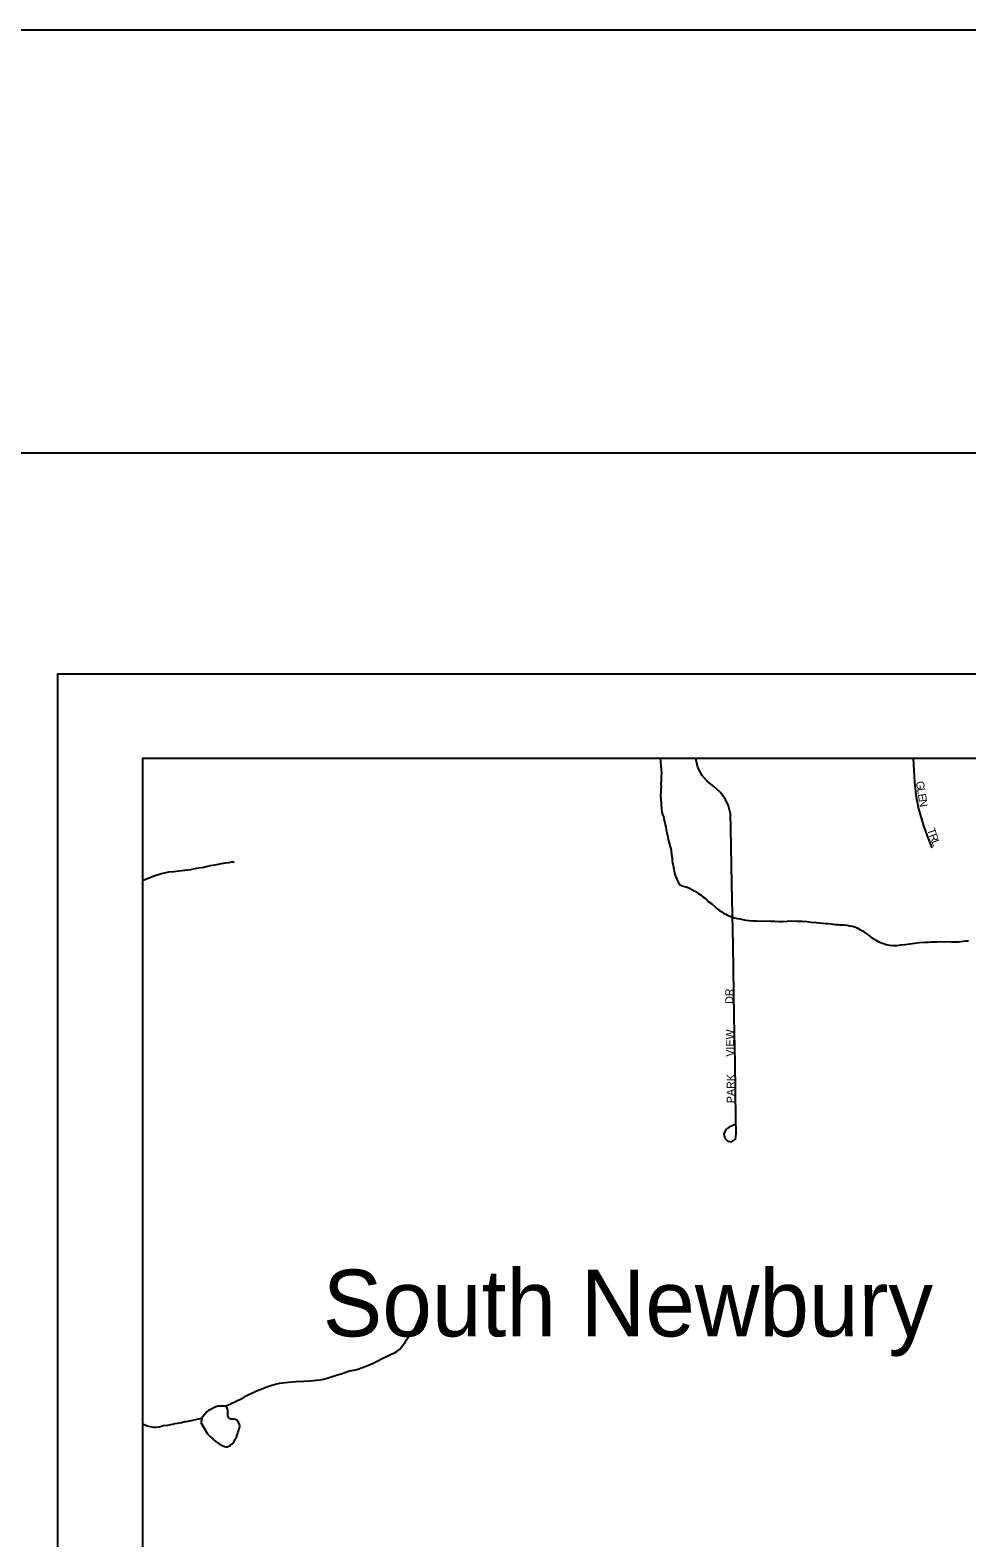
# Model space of a CAD drawing. Extents: x 0 to 34, y 0 to 22.
# Drawn here: x 2.229 to 3.337, y 20.216 to 22 of the extents above; entities that cross this region are included whole.
import ezdxf

# ---------------------------------------------------------------- set-up
doc = ezdxf.new("R2010")
doc.units = 0
for name, color, linetype in [('GM_X_County', 7, 'Continuous'), ('GM_X_Minor_Lake', 7, 'Continuous'), ('GM_X_Minor_River', 7, 'Continuous'), ('GM_X_Township', 7, 'Continuous'), ('GM_X_Township_Subdivision', 7, 'Continuous'), ('GM_X_Township_Subdivision_Text', 7, 'Continuous'), ('GM_X_Unincorporated_Text', 7, 'Continuous'), ('SH_Border', 7, 'Continuous'), ('SH_Cut_Line', 7, 'Continuous'), ('SH_Data', 7, 'Continuous')]:
    doc.layers.add(name, color=color, linetype=linetype)

msp = doc.modelspace()

# ---------------------------------------------------------------- linework, layer by layer
at = {"layer": 'GM_X_County'}
msp.add_lwpolyline([(9.1622, 14.342), (9.1622, 21.1385), (2.3622, 21.1385), (2.3622, 14.3385), (9.0003, 14.3385)], dxfattribs=at)
at = {"layer": 'GM_X_Minor_Lake'}
for points in [[(2.4565, 20.3721), (2.4538, 20.3722), (2.4515, 20.3721), (2.4489, 20.3713), (2.4455, 20.3697), (2.4428, 20.3681), (2.4406, 20.3673), (2.438, 20.3654), (2.4357, 20.3627), (2.4342, 20.3607), (2.4324, 20.358), (2.4317, 20.355), (2.431, 20.3527)], [(2.431, 20.3527), (2.4389, 20.3392), (2.4408, 20.3373), (2.4428, 20.3355), (2.4455, 20.3332), (2.4474, 20.3314), (2.4494, 20.3299), (2.4517, 20.3284), (2.4544, 20.3266), (2.4571, 20.3251), (2.4605, 20.3241), (2.4624, 20.3241), (2.4658, 20.3257), (2.4681, 20.3277), (2.4707, 20.3304), (2.4717, 20.3331), (2.4732, 20.3354), (2.4743, 20.3388), (2.475, 20.3407), (2.4761, 20.3442), (2.4768, 20.3465), (2.4771, 20.3484), (2.4767, 20.3503), (2.4759, 20.3525), (2.4743, 20.3552), (2.472, 20.3562), (2.4701, 20.3566), (2.4667, 20.3565), (2.4644, 20.3584), (2.4632, 20.3606), (2.4631, 20.3629), (2.4631, 20.3652), (2.463, 20.3674), (2.4622, 20.3697), (2.4603, 20.3719), (2.4565, 20.3721)]]:
    msp.add_lwpolyline(points, dxfattribs=at)
at = {"layer": 'GM_X_Minor_River'}
for points in [[(2.9745, 21.1385), (2.9745, 21.1381), (2.975, 21.1355), (2.975, 21.1332), (2.9755, 21.1302), (2.9759, 21.1256), (2.976, 21.1211), (2.9757, 21.1165), (2.9758, 21.1123), (2.9755, 21.1081), (2.9756, 21.1051), (2.9753, 21.1028), (2.9753, 21.1005), (2.9754, 21.0986), (2.9751, 21.0956), (2.9751, 21.0933), (2.9752, 21.0906), (2.9752, 21.0887), (2.9756, 21.0857), (2.9757, 21.0838), (2.9762, 21.0789), (2.9766, 21.0747), (2.9775, 21.0721), (2.9783, 21.0698), (2.9787, 21.0672), (2.9791, 21.0653), (2.9799, 21.0626), (2.9804, 21.06), (2.9812, 21.0573), (2.9816, 21.0539), (2.9825, 21.0509), (2.9833, 21.0471), (2.9842, 21.0426), (2.9854, 21.0369), (2.9867, 21.0328), (2.9875, 21.0297), (2.9875, 21.0278), (2.988, 21.0252), (2.9889, 21.0195), (2.9889, 21.0176), (2.9893, 21.0146), (2.9898, 21.0119), (2.9906, 21.0074), (2.9915, 21.0028), (2.9927, 20.9991), (2.9943, 20.9957), (2.9951, 20.9934), (2.9963, 20.9912), (2.9975, 20.9893), (3.0006, 20.9878), (3.0032, 20.9868), (3.0063, 20.9861)], [(2.3622, 20.9939), (2.3768, 20.9997), (2.3806, 21.001), (2.3844, 21.0022), (2.3885, 21.003), (2.3934, 21.0043), (2.3991, 21.0048), (2.4052, 21.0053), (2.412, 21.0062), (2.4193, 21.0071), (2.4261, 21.0084), (2.4348, 21.0097), (2.4424, 21.0118), (2.4499, 21.0131), (2.4556, 21.014), (2.4602, 21.0148), (2.4643, 21.0153), (2.4678, 21.0162), (2.4693, 21.0162), (2.4704, 21.0162)], [(3.0063, 20.9861), (3.0094, 20.985), (3.0121, 20.9835), (3.0155, 20.9813), (3.019, 20.9791), (3.0221, 20.9769), (3.0252, 20.9747), (3.0283, 20.9725), (3.0314, 20.9691), (3.0356, 20.9662), (3.0391, 20.9632), (3.0418, 20.9606), (3.0449, 20.9584), (3.0476, 20.957), (3.05, 20.9551), (3.0523, 20.954), (3.0542, 20.9529), (3.0561, 20.9522), (3.058, 20.9515), (3.0599, 20.9508), (3.0622, 20.95), (3.0642, 20.9493), (3.0661, 20.949), (3.0687, 20.9487), (3.0706, 20.9483), (3.0741, 20.9476), (3.0764, 20.9469), (3.0798, 20.9466), (3.084, 20.9463), (3.0886, 20.9461), (3.1053, 20.9457), (3.1103, 20.9458), (3.1152, 20.9455), (3.1198, 20.9456), (3.1247, 20.9457), (3.1304, 20.9462), (3.1365, 20.946), (3.1426, 20.9457), (3.1483, 20.9455), (3.1533, 20.9448), (3.159, 20.9442), (3.1632, 20.9439), (3.167, 20.9436), (3.1704, 20.9433), (3.1735, 20.943), (3.1765, 20.9427), (3.1792, 20.9423), (3.1819, 20.942), (3.1849, 20.9421), (3.1872, 20.9417), (3.1891, 20.9414), (3.1914, 20.9415), (3.1956, 20.9412), (3.1986, 20.9405), (3.2021, 20.9398), (3.2047, 20.9391), (3.2078, 20.938), (3.2109, 20.9362), (3.214, 20.9344), (3.2175, 20.9318), (3.2209, 20.9292), (3.2248, 20.9262), (3.2287, 20.924), (3.2333, 20.9215), (3.2363, 20.9204), (3.239, 20.9193), (3.2421, 20.9182), (3.2459, 20.9176), (3.2497, 20.9169), (3.2543, 20.917), (3.2592, 20.9179), (3.2645, 20.9184), (3.2698, 20.9192), (3.2755, 20.9197), (3.2812, 20.9206), (3.2881, 20.9211), (3.2919, 20.9212), (3.2953, 20.9213), (3.2987, 20.9214), (3.3021, 20.9215), (3.3151, 20.9217), (3.3192, 20.9214), (3.3234, 20.9215), (3.3276, 20.9216), (3.3329, 20.9221), (3.3367, 20.9226), (3.3394, 20.9226)], [(2.4603, 20.3719), (2.4787, 20.3807), (2.481, 20.3819), (2.484, 20.3839), (2.4877, 20.3858), (2.4923, 20.3878), (2.4971, 20.3902), (2.5024, 20.3922), (2.5073, 20.3942), (2.5126, 20.3963), (2.5179, 20.3979), (2.5243, 20.3992), (2.535, 20.4005), (2.5437, 20.4011), (2.5528, 20.4017), (2.5608, 20.4022), (2.5676, 20.4028), (2.5726, 20.4033), (2.5764, 20.4041), (2.5805, 20.4053), (2.5854, 20.4066), (2.5915, 20.4086), (2.5983, 20.4107), (2.6058, 20.4135), (2.6157, 20.4156), (2.6225, 20.418), (2.6293, 20.4205), (2.6349, 20.4229), (2.6406, 20.4256), (2.6458, 20.4284), (2.6507, 20.4308), (2.6556, 20.4332), (2.6601, 20.4352), (2.6635, 20.4372), (2.6661, 20.4391), (2.6687, 20.4418), (2.6702, 20.4441), (2.6724, 20.4472), (2.6746, 20.4507), (2.6769, 20.4542), (2.6791, 20.4576), (2.6813, 20.4603), (2.6831, 20.4627), (2.685, 20.4654), (2.6864, 20.4681), (2.6879, 20.4711), (2.6893, 20.4753), (2.6911, 20.4796), (2.6929, 20.4842), (2.6947, 20.4888), (2.6962, 20.4914), (2.6977, 20.4949), (2.698, 20.4953), (2.698, 20.4957)], [(2.3622, 20.351), (2.3652, 20.3501), (2.3676, 20.349), (2.371, 20.348), (2.3752, 20.3473), (2.3779, 20.3474), (2.3817, 20.3478), (2.3866, 20.3491), (2.3919, 20.3496), (2.3957, 20.3504), (2.3976, 20.3508), (2.4002, 20.3516), (2.4036, 20.3521), (2.4059, 20.3525)], [(2.4059, 20.3525), (2.4082, 20.3526), (2.412, 20.3538), (2.4139, 20.3538), (2.4161, 20.3543), (2.4324, 20.358)]]:
    msp.add_lwpolyline(points, dxfattribs=at)
at = {"layer": 'GM_X_Township'}
msp.add_lwpolyline([(4.3953, 21.1385), (2.3622, 21.1385), (2.3622, 19.6335)], dxfattribs=at)
at = {"layer": 'GM_X_Township_Subdivision'}
for points in [[(3.0642, 20.7058), (3.0561, 20.7021), (3.0522, 20.6994), (3.0499, 20.6942), (3.051, 20.6893), (3.0545, 20.6854), (3.059, 20.6847), (3.0636, 20.6878), (3.0644, 20.6947), (3.064, 20.7126), (3.0634, 20.7782), (3.0621, 20.8326), (3.0611, 20.9171), (3.0594, 20.9906), (3.0582, 21.0559), (3.0576, 21.0729), (3.0555, 21.0824), (3.0518, 21.09), (3.0458, 21.0981), (3.0379, 21.1051), (3.0305, 21.1111), (3.0243, 21.1181), (3.0191, 21.1276), (3.0173, 21.1363), (3.0172, 21.1385)], [(3.2737, 21.1385), (3.2745, 21.1245), (3.2753, 21.1103), (3.2772, 21.0952), (3.2803, 21.0786), (3.2861, 21.0586), (3.2902, 21.0476), (3.2958, 21.0327)]]:
    msp.add_lwpolyline(points, dxfattribs=at)
at = {"layer": 'SH_Border'}
msp.add_lwpolyline([(2, 21.5), (33.5, 21.5), (33.5, 0.5), (2, 0.5)], close=True, dxfattribs=at)
at = {"layer": 'SH_Cut_Line'}
msp.add_lwpolyline([(0, 0), (34, 0), (34, 22), (0, 22)], close=True, dxfattribs=at)
at = {"layer": 'SH_Data'}
for q in [(9.2617, 21.2383), (2.2617, 14.2383)]:
    msp.add_line((2.2617, 21.2383), q, dxfattribs=at)

# ---------------------------------------------------------------- texts
at = {"layer": 'GM_X_Township_Subdivision_Text'}
for s, rotation, p in [('G', 279.0419, (3.277, 21.1108)), ('L', 279.0541, (3.2784, 21.1026)), ('E', 279.0536, (3.2794, 21.096)), ('N', 279.7165, (3.2805, 21.0893)), ('T', 287.3377, (3.2903, 21.0543)), ('R', 290.7235, (3.2925, 21.0474)), ('L', 291.2586, (3.2952, 21.0402)), ('DR', 90, (3.061, 20.848)), ('VIEW', 90, (3.0618, 20.7855)), ('PARK', 90, (3.0627, 20.7305))]:
    msp.add_text(s, height=0.00947, rotation=rotation, dxfattribs=at).set_placement(p)
at = {"layer": 'GM_X_Unincorporated_Text'}
msp.add_text('South Newbury', height=0.078977, rotation=0, dxfattribs=at).set_placement((2.5753, 20.4546))

doc.saveas('drawing.dxf')
